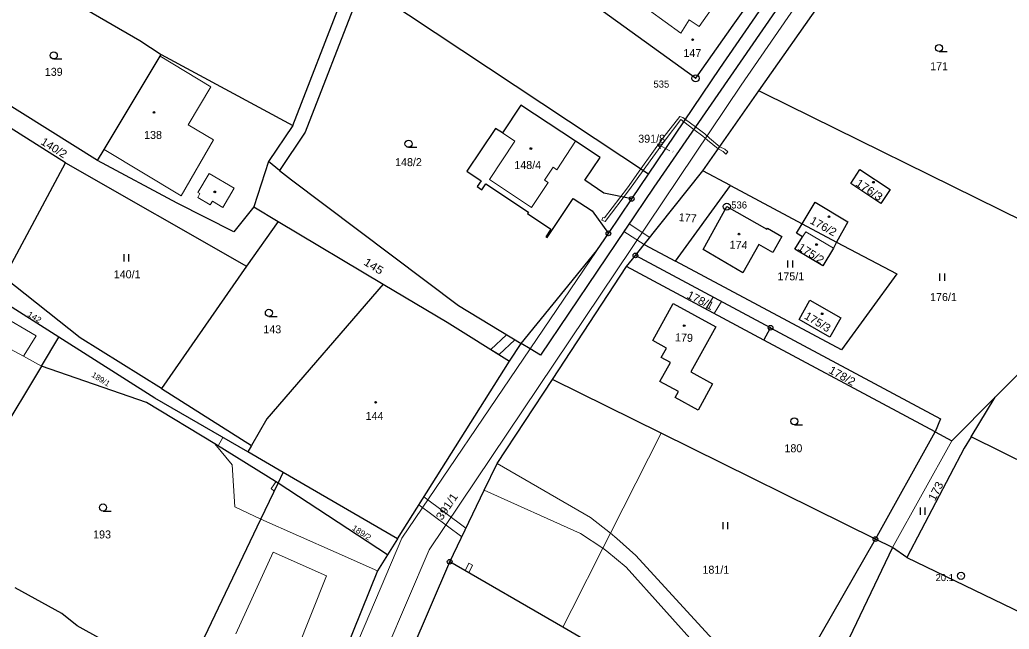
# Model space of a CAD drawing. Extents: x -504006 to -501322, y -1128098 to -1124665.
# Drawn here: x -502549.5 to -502339.3, y -1126661.3 to -1126531.9 of the extents above; entities that cross this region are included whole.
import ezdxf
from ezdxf.enums import TextEntityAlignment as Align

# ---------------------------------------------------------------- set-up
doc = ezdxf.new("R2010")
doc.units = 0
doc.header["$LTSCALE"] = 0.68
for name, color, linetype, lineweight in [('1', 7, 'Continuous', 25), ('13', 7, 'Continuous', 13), ('3', 7, 'Continuous', 25), ('4', 7, 'Continuous', 13), ('5', 7, 'Continuous', 25), ('7', 7, 'Continuous', 13), ('8', 7, 'Continuous', 25)]:
    doc.layers.add(name, color=color, linetype=linetype, lineweight=lineweight)
doc.layers.add('2', color=7, linetype='Continuous')

msp = doc.modelspace()

# ---------------------------------------------------------------- linework, layer by layer
at = {"layer": '1'}
for p, q in [((-502491.56, -1126554.34), (-502465.06, -1126486.12)), ((-502392.52, -1126547.01), (-502363.8, -1126506.1)), ((-502400.8, -1126542.27), (-502379.33, -1126511.02)), ((-502384.2, -1126523.11), (-502414.86, -1126567.45)), ((-502544.69, -1126524.32), (-502524.07, -1126536.28)), ((-502476.73, -1126524.43), (-502488.89, -1126555.75)), ((-502415.96, -1126564.65), (-502476.73, -1126524.43)), ((-502405.98, -1126544.33), (-502427.32, -1126528.97)), ((-502398.02, -1126533.04), (-502405.98, -1126544.33)), ((-502524.07, -1126536.28), (-502519.51, -1126539.28)), ((-502531.61, -1126559.43), (-502519.72, -1126539.62)), ((-502519.72, -1126539.62), (-502519.51, -1126539.28)), ((-502519.51, -1126539.28), (-502491.56, -1126554.34)), ((-502533.04, -1126561.8), (-502565.3, -1126541.54)), ((-502415.96, -1126564.65), (-502400.8, -1126542.27)), ((-502539.8, -1126562.27), (-502568.05, -1126544.45)), ((-502404.41, -1126563.95), (-502392.52, -1126547.01)), ((-502391.37, -1126547.57), (-502392.52, -1126547.01)), ((-502336.24, -1126574.75), (-502391.37, -1126547.57)), ((-502443.1, -1126550.02), (-502447, -1126555.93)), ((-502431.49, -1126557.7), (-502443.1, -1126550.02)), ((-502491.56, -1126554.34), (-502496.68, -1126562.02)), ((-502448.5, -1126554.96), (-502454.57, -1126564.07)), ((-502447, -1126555.93), (-502448.5, -1126554.96)), ((-502488.89, -1126555.75), (-502494.33, -1126563.91)), ((-502533.04, -1126561.8), (-502531.61, -1126559.43)), ((-502426.26, -1126561.18), (-502431.49, -1126557.7)), ((-502516.1, -1126570.87), (-502533.04, -1126561.8)), ((-502429.47, -1126565.99), (-502426.26, -1126561.18)), ((-502552.84, -1126586.64), (-502539.8, -1126562.27)), ((-502539.8, -1126562.27), (-502501.36, -1126584.22)), ((-502496.68, -1126562.02), (-502499.83, -1126571.64)), ((-502494.33, -1126563.91), (-502496.68, -1126562.02)), ((-502494.33, -1126563.91), (-502491.84, -1126565.92)), ((-502416.88, -1126579.61), (-502404.41, -1126563.95)), ((-502398.54, -1126567.07), (-502404.41, -1126563.95)), ((-502372.97, -1126566.7), (-502371.1, -1126563.66)), ((-502371.1, -1126563.66), (-502364.64, -1126567.93)), ((-502491.84, -1126565.92), (-502456.31, -1126592.6)), ((-502454.57, -1126564.07), (-502451.51, -1126566.08)), ((-502451.51, -1126566.08), (-502452.39, -1126567.33)), ((-502425.44, -1126568.69), (-502429.47, -1126565.99)), ((-502419.54, -1126569.95), (-502415.96, -1126564.65)), ((-502452.39, -1126567.33), (-502451.39, -1126568.01)), ((-502451.39, -1126568.01), (-502450.53, -1126566.75)), ((-502450.53, -1126566.75), (-502441.45, -1126572.74)), ((-502414.86, -1126567.45), (-502438.93, -1126603.12)), ((-502410.26, -1126583.15), (-502398.54, -1126567.07)), ((-502398.54, -1126567.07), (-502383.35, -1126575.2)), ((-502366.61, -1126570.91), (-502372.97, -1126566.7)), ((-502364.64, -1126567.93), (-502366.61, -1126570.91)), ((-502437.48, -1126578.1), (-502432, -1126569.82)), ((-502432, -1126569.82), (-502427.93, -1126572.47)), ((-502419.54, -1126569.95), (-502425.44, -1126568.69)), ((-502424.49, -1126577.25), (-502419.54, -1126569.95)), ((-502504.09, -1126576.9), (-502516.1, -1126570.87)), ((-502499.83, -1126571.64), (-502504.09, -1126576.9)), ((-502499.83, -1126571.64), (-502494.68, -1126574.71)), ((-502404.37, -1126580.7), (-502399.33, -1126571.57)), ((-502399.33, -1126571.57), (-502390.84, -1126576.39)), ((-502383.35, -1126575.2), (-502380.59, -1126570.6)), ((-502380.59, -1126570.6), (-502373.61, -1126574.8)), ((-502441.45, -1126572.74), (-502441.69, -1126573.07)), ((-502441.69, -1126573.07), (-502436.71, -1126576.35)), ((-502427.93, -1126572.47), (-502424.49, -1126577.25)), ((-502494.68, -1126574.71), (-502501.36, -1126584.22)), ((-502494.68, -1126574.71), (-502472.34, -1126588.01)), ((-502436.71, -1126576.35), (-502437.76, -1126577.98)), ((-502390.84, -1126576.39), (-502390.71, -1126576.17)), ((-502390.71, -1126576.17), (-502387.64, -1126577.91)), ((-502384.56, -1126577.21), (-502383.35, -1126575.2)), ((-502383.35, -1126575.2), (-502376, -1126579.13)), ((-502373.61, -1126574.8), (-502376, -1126579.13)), ((-502437.76, -1126577.98), (-502437.48, -1126578.1)), ((-502426.96, -1126580.9), (-502424.49, -1126577.25)), ((-502387.64, -1126577.91), (-502389.57, -1126581.3)), ((-502384.91, -1126580.64), (-502383.25, -1126577.98)), ((-502383.25, -1126577.98), (-502384.56, -1126577.21)), ((-502418.75, -1126581.95), (-502416.88, -1126579.61)), ((-502416.88, -1126579.61), (-502410.26, -1126583.15)), ((-502395.93, -1126585.65), (-502404.37, -1126580.7)), ((-502392.53, -1126579.63), (-502395.93, -1126585.65)), ((-502389.57, -1126581.3), (-502392.53, -1126579.63)), ((-502378.94, -1126584.18), (-502384.91, -1126580.64)), ((-502376.69, -1126580.38), (-502378.94, -1126584.18)), ((-502376, -1126579.13), (-502376.69, -1126580.38)), ((-502376, -1126579.13), (-502363.21, -1126585.83)), ((-502443.03, -1126600.64), (-502426.96, -1126580.9)), ((-502420.61, -1126584.3), (-502418.75, -1126581.95)), ((-502390.04, -1126597.31), (-502418.75, -1126581.95)), ((-502501.36, -1126584.22), (-502519.41, -1126610.18)), ((-502436.36, -1126608.25), (-502420.61, -1126584.3)), ((-502391.46, -1126599.92), (-502420.61, -1126584.3)), ((-502374.97, -1126602.01), (-502410.26, -1126583.15)), ((-502536.69, -1126599.46), (-502552.84, -1126586.64)), ((-502363.21, -1126585.83), (-502374.97, -1126602.01)), ((-502472.34, -1126588.01), (-502497.08, -1126616.67)), ((-502472.34, -1126588.01), (-502458.73, -1126596.12)), ((-502342.31, -1126612.01), (-502317.72, -1126587.26)), ((-502541.25, -1126599.31), (-502554.98, -1126590.62)), ((-502456.31, -1126592.6), (-502443.03, -1126600.64)), ((-502415.05, -1126600.03), (-502410.72, -1126592.13)), ((-502410.72, -1126592.13), (-502401.7, -1126597.07)), ((-502383.98, -1126595.53), (-502381.69, -1126591.45)), ((-502381.69, -1126591.45), (-502375.13, -1126595.21)), ((-502375.13, -1126595.21), (-502377.48, -1126599.3)), ((-502458.73, -1126596.12), (-502445.53, -1126604.37)), ((-502401.7, -1126597.07), (-502406.97, -1126606.69)), ((-502391.46, -1126599.92), (-502390.04, -1126597.31)), ((-502390.04, -1126597.31), (-502353.91, -1126616.65)), ((-502377.48, -1126599.3), (-502383.98, -1126595.53)), ((-502544.95, -1126605.46), (-502541.25, -1126599.31)), ((-502520.84, -1126612.23), (-502541.25, -1126599.31)), ((-502519.41, -1126610.18), (-502536.69, -1126599.46)), ((-502445.53, -1126604.37), (-502443.03, -1126600.64)), ((-502441.12, -1126601.8), (-502443.03, -1126600.64)), ((-502438.93, -1126603.12), (-502441.12, -1126601.8)), ((-502412.17, -1126601.61), (-502415.05, -1126600.03)), ((-502413.26, -1126603.6), (-502412.17, -1126601.61)), ((-502411.33, -1126604.66), (-502413.26, -1126603.6)), ((-502544.95, -1126605.46), (-502554.24, -1126620.87)), ((-502522.59, -1126613.18), (-502544.95, -1126605.46)), ((-502469.29, -1126642.13), (-502445.53, -1126604.37)), ((-502413.55, -1126608.7), (-502411.33, -1126604.66)), ((-502406.97, -1126606.69), (-502402.36, -1126609.22)), ((-502519.41, -1126610.18), (-502500.34, -1126622.32)), ((-502448.12, -1126626.12), (-502436.36, -1126608.25)), ((-502413.29, -1126619.66), (-502436.36, -1126608.25)), ((-502409.63, -1126610.84), (-502413.55, -1126608.7)), ((-502402.36, -1126609.22), (-502405.4, -1126614.77)), ((-502501.12, -1126623.67), (-502520.84, -1126612.23)), ((-502410.31, -1126612.08), (-502409.63, -1126610.84)), ((-502405.4, -1126614.77), (-502410.31, -1126612.08)), ((-502351.55, -1126621.3), (-502342.31, -1126612.01)), ((-502347.44, -1126620.43), (-502342.31, -1126612.01)), ((-502508.13, -1126621.92), (-502522.59, -1126613.18)), ((-502497.08, -1126616.67), (-502500.34, -1126622.32)), ((-502367.75, -1126642.18), (-502413.29, -1126619.66)), ((-502367.75, -1126642.18), (-502355.08, -1126619.41)), ((-502355.08, -1126619.41), (-502351.55, -1126621.3)), ((-502347.44, -1126620.43), (-502348.93, -1126622.89)), ((-502331.98, -1126628.1), (-502347.44, -1126620.43)), ((-502494.68, -1126630.29), (-502508.13, -1126621.92)), ((-502500.34, -1126622.32), (-502501.12, -1126623.67)), ((-502493.6, -1126628.03), (-502501.12, -1126623.67)), ((-502348.93, -1126622.89), (-502361.11, -1126646.11)), ((-502450.87, -1126631.81), (-502448.12, -1126626.12)), ((-502494.68, -1126630.29), (-502493.6, -1126628.03)), ((-502469.29, -1126642.13), (-502493.6, -1126628.03)), ((-502498.34, -1126637.96), (-502494.68, -1126630.29)), ((-502471.42, -1126645.51), (-502494.68, -1126630.29)), ((-502458.21, -1126646.98), (-502450.87, -1126631.81)), ((-502514.61, -1126672.05), (-502498.34, -1126637.96)), ((-502469.29, -1126642.13), (-502471.42, -1126645.51)), ((-502388.53, -1126678.42), (-502367.75, -1126642.18)), ((-502364.16, -1126643.95), (-502367.75, -1126642.18)), ((-502471.42, -1126645.51), (-502473.55, -1126648.9)), ((-502361.11, -1126646.11), (-502364.16, -1126643.95)), ((-502468.87, -1126671.79), (-502458.21, -1126646.98)), ((-502434.16, -1126660.88), (-502458.21, -1126646.98)), ((-502361.11, -1126646.11), (-502297.3, -1126676.83)), ((-502473.55, -1126648.9), (-502487.98, -1126684.63)), ((-502540.59, -1126658), (-502550.55, -1126652.54)), ((-502537.38, -1126660.61), (-502540.59, -1126658)), ((-502532.13, -1126663.52), (-502537.38, -1126660.61)), ((-502394.44, -1126683.84), (-502434.16, -1126660.88))]:
    msp.add_line(p, q, dxfattribs=at)
for points in [[(-502382.43, -1126510.29), (-502390.84, -1126522.88), (-502398.02, -1126533.04)], [(-502353.91, -1126616.65), (-502355.08, -1126619.41), (-502391.46, -1126599.92)], [(-502364.16, -1126643.95), (-502383.3, -1126684.1), (-502385.94, -1126688.76)]]:
    msp.add_lwpolyline(points, dxfattribs=at)
at = {"layer": '13'}
for points in [[(-502408.44, -1126553.55), (-502408.13, -1126553.09), (-502408.68, -1126552.65), (-502409.34, -1126552.46), (-502412.96, -1126557.07), (-502417.61, -1126563.56), (-502417.1, -1126563.9), (-502412.45, -1126557.45), (-502409.08, -1126553.1)], [(-502408.13, -1126553.09), (-502408.44, -1126553.55), (-502406.37, -1126555.17), (-502404.42, -1126556.6), (-502403.41, -1126557.47), (-502401.15, -1126559.31), (-502400.83, -1126558.85), (-502403.04, -1126557.03), (-502404.03, -1126556.11), (-502406.01, -1126554.65)], [(-502400.83, -1126558.85), (-502401.15, -1126559.31), (-502400.14, -1126559.85), (-502399.51, -1126560.43), (-502399.15, -1126559.97), (-502399.76, -1126559.38)], [(-502425.64, -1126573.87), (-502425.86, -1126574.44), (-502425.15, -1126574.71), (-502420.02, -1126567.93), (-502417.1, -1126563.9), (-502417.61, -1126563.56), (-502420.46, -1126567.57), (-502425.35, -1126573.98)], [(-502415.7, -1126578.13), (-502420.11, -1126575.23), (-502421.2, -1126576.84), (-502416.88, -1126579.61)], [(-502402.25, -1126590.78), (-502403.8, -1126593.31), (-502402.03, -1126594.26), (-502400.48, -1126591.72)], [(-502446.13, -1126598.77), (-502449.47, -1126601.91), (-502447.72, -1126603), (-502444.35, -1126599.84)], [(-502507.42, -1126622.36), (-502494.68, -1126630.29), (-502493.6, -1126628.03), (-502501.12, -1126623.67), (-502506.4, -1126620.61)], [(-502496.15, -1126631.45), (-502495.5, -1126632), (-502494.68, -1126630.29), (-502495.15, -1126630), (-502495.68, -1126630.86)], [(-502454.75, -1126639.83), (-502463.68, -1126633.22), (-502464.75, -1126634.91), (-502455.64, -1126641.66)], [(-502454.9, -1126648.89), (-502454.11, -1126649.35), (-502453.35, -1126647.72), (-502454.14, -1126647.29)]]:
    msp.add_lwpolyline(points, close=True, dxfattribs=at)
at = {"layer": '3'}
for p, q in [((-502354.243, -1126538.65), (-502352.493, -1126538.65)), ((-502542.323, -1126540.22), (-502540.573, -1126540.22)), ((-502466.953, -1126558.98), (-502465.203, -1126558.98)), ((-502527.381, -1126583.2), (-502527.381, -1126581.7)), ((-502526.38, -1126583.2), (-502526.38, -1126581.7)), ((-502386.341, -1126584.5), (-502386.341, -1126583)), ((-502385.34, -1126584.5), (-502385.34, -1126583)), ((-502354.051, -1126587.3), (-502354.051, -1126585.8)), ((-502353.05, -1126587.3), (-502353.05, -1126585.8)), ((-502496.613, -1126594.88), (-502494.863, -1126594.88)), ((-502384.983, -1126617.91), (-502383.233, -1126617.91)), ((-502531.853, -1126636.21), (-502530.103, -1126636.21)), ((-502358.211, -1126636.99), (-502358.211, -1126635.49)), ((-502357.21, -1126636.99), (-502357.21, -1126635.49)), ((-502400.091, -1126640.07), (-502400.091, -1126638.57)), ((-502399.09, -1126640.07), (-502399.09, -1126638.57))]:
    msp.add_line(p, q, dxfattribs=at)
for centre in [(-502542.3229, -1126539.4698), (-502354.2429, -1126537.8998), (-502466.9529, -1126558.2298), (-502496.6129, -1126594.1298), (-502384.9829, -1126617.1598), (-502531.8529, -1126635.4598)]:
    msp.add_circle(centre, 0.75, dxfattribs=at)
at = {"layer": '4'}
for p, q in [((-502370.24, -1126508), (-502396.3, -1126545.8)), ((-502405.22, -1126533.31), (-502399.58, -1126525.35)), ((-502419.12, -1126527.46), (-502409.09, -1126534.74)), ((-502409.09, -1126534.74), (-502407.3, -1126531.91)), ((-502407.3, -1126531.91), (-502405.22, -1126533.31)), ((-502519.72, -1126539.62), (-502508.94, -1126546.13)), ((-502508.94, -1126546.13), (-502513.8, -1126554.23)), ((-502396.3, -1126545.8), (-502462.54, -1126644.48)), ((-502513.8, -1126554.23), (-502508.36, -1126557.38)), ((-502508.36, -1126557.38), (-502515.23, -1126569.25)), ((-502449.77, -1126565.8), (-502444.38, -1126557.67)), ((-502444.38, -1126557.67), (-502447, -1126555.93)), ((-502515.23, -1126569.25), (-502531.61, -1126559.43)), ((-502431.49, -1126557.7), (-502435.48, -1126563.73)), ((-502436.24, -1126563.23), (-502438.04, -1126565.94)), ((-502435.48, -1126563.73), (-502436.24, -1126563.23)), ((-502511.68, -1126568.58), (-502509.28, -1126564.53)), ((-502509.28, -1126564.53), (-502504.02, -1126567.64)), ((-502440.81, -1126571.75), (-502449.77, -1126565.8)), ((-502438.04, -1126565.94), (-502437.29, -1126566.43)), ((-502504.02, -1126567.64), (-502506.39, -1126571.78)), ((-502437.29, -1126566.43), (-502440.81, -1126571.75)), ((-502511.74, -1126569.62), (-502511.27, -1126568.82)), ((-502509.07, -1126571.23), (-502511.74, -1126569.62)), ((-502511.27, -1126568.82), (-502511.68, -1126568.58)), ((-502508.59, -1126570.45), (-502509.07, -1126571.23)), ((-502506.39, -1126571.78), (-502508.59, -1126570.45)), ((-502383.25, -1126577.98), (-502382.58, -1126576.9)), ((-502382.58, -1126576.9), (-502376.69, -1126580.38)), ((-502441.12, -1126601.8), (-502426.96, -1126580.9)), ((-502553.84, -1126594.48), (-502546.08, -1126598.99)), ((-502548.78, -1126603.34), (-502556.72, -1126599.01)), ((-502546.08, -1126598.99), (-502548.64, -1126603.12)), ((-502468.35, -1126642), (-502441.12, -1126601.8)), ((-502548.64, -1126603.12), (-502548.78, -1126603.34)), ((-502548.78, -1126603.34), (-502544.95, -1126605.46)), ((-502424.04, -1126640.9), (-502413.29, -1126619.66)), ((-502508.13, -1126621.92), (-502504.39, -1126626.43)), ((-502351.55, -1126621.3), (-502364.16, -1126643.95)), ((-502504.39, -1126626.43), (-502503.86, -1126635.33)), ((-502448.12, -1126626.12), (-502428.27, -1126637.61)), ((-502450.87, -1126631.81), (-502430.42, -1126640.99)), ((-502503.86, -1126635.33), (-502498.34, -1126637.96)), ((-502498.34, -1126637.96), (-502482.36, -1126645.01)), ((-502424.04, -1126640.9), (-502428.27, -1126637.61)), ((-502430.42, -1126640.99), (-502425.66, -1126644.09)), ((-502425.66, -1126644.09), (-502424.04, -1126640.9)), ((-502422.69, -1126642.08), (-502424.04, -1126640.9)), ((-502468.35, -1126642), (-502488.41, -1126689.01)), ((-502418.68, -1126645.66), (-502422.69, -1126642.08)), ((-502503.66, -1126662.3), (-502495.74, -1126644.98)), ((-502495.74, -1126644.98), (-502484.35, -1126649.98)), ((-502462.54, -1126644.48), (-502482.56, -1126690.99)), ((-502482.36, -1126645.01), (-502473.55, -1126648.9)), ((-502432.26, -1126657.13), (-502425.66, -1126644.09)), ((-502425.66, -1126644.09), (-502424.82, -1126644.72)), ((-502424.82, -1126644.72), (-502420.74, -1126648.16)), ((-502418.68, -1126645.66), (-502388.53, -1126678.42)), ((-502484.35, -1126649.98), (-502492.98, -1126671.58)), ((-502420.74, -1126648.16), (-502390.44, -1126681.76)), ((-502434.16, -1126660.88), (-502432.26, -1126657.13))]:
    msp.add_line(p, q, dxfattribs=at)
at = {"layer": '5'}
for centre in [(-502406.5968, -1126536.1292), (-502521.0268, -1126551.5792), (-502440.9668, -1126559.2492), (-502368.1768, -1126566.3892), (-502508.1168, -1126568.4392), (-502377.6368, -1126573.7392), (-502396.7368, -1126577.4192), (-502380.2768, -1126579.6292), (-502379.0768, -1126594.3292), (-502408.3868, -1126596.8492), (-502473.9468, -1126613.1192)]:
    msp.add_circle(centre, 0.175, dxfattribs=at)
at = {"layer": '7'}
msp.add_line((-502414.065, -1126558.295), (-502413.432, -1126559.219), dxfattribs=at)
msp.add_lwpolyline([(-502411.44, -1126559.75), (-502414.065, -1126558.295), (-502412.946, -1126558.343)], dxfattribs=at)
at = {"layer": '8'}
for centre, radius in [((-502405.98, -1126544.3298), 0.75), ((-502405.98, -1126544.3298), 0.03), ((-502419.54, -1126569.9499), 0.5), ((-502419.54, -1126569.9499), 0.0303), ((-502399.33, -1126571.5698), 0.75), ((-502399.33, -1126571.5698), 0.03), ((-502424.49, -1126577.2499), 0.5), ((-502424.49, -1126577.2499), 0.0303), ((-502418.75, -1126581.9499), 0.5), ((-502418.75, -1126581.9499), 0.0303), ((-502390.04, -1126597.3099), 0.5), ((-502390.04, -1126597.3099), 0.0303), ((-502367.75, -1126642.1799), 0.5), ((-502367.75, -1126642.1799), 0.0303), ((-502458.21, -1126646.9799), 0.5), ((-502458.21, -1126646.9799), 0.0303), ((-502349.58, -1126649.9798), 0.75), ((-502349.58, -1126649.9798), 0.03)]:
    msp.add_circle(centre, radius, dxfattribs=at)

# ---------------------------------------------------------------- texts
at = {"layer": '2'}
for s, p in [('147', (-502406.649, -1126539.805)), ('139', (-502542.329, -1126543.805)), ('171', (-502354.239, -1126542.625)), ('138', (-502521.229, -1126557.205)), ('148/2', (-502466.96, -1126562.985)), ('148/4', (-502441.63, -1126563.595)), ('140/1', (-502526.73, -1126586.795)), ('175/1', (-502385.74, -1126587.225)), ('176/1', (-502353.31, -1126591.625)), ('143', (-502495.899, -1126598.475)), ('144', (-502474.179, -1126616.875)), ('180', (-502385.189, -1126623.735)), ('193', (-502532.059, -1126642.035)), ('181/1', (-502401.66, -1126649.525))]:
    msp.add_text(s, height=1.7, dxfattribs=at).set_placement(p, align=Align.CENTER)
for s, height, rotation, width, p in [('140/2', 1.7, 328, 1.05, (-502542.7159, -1126559.8029)), ('391/8', 0.2, 56, 1.1, (-502410.7492, -1126560.0889)), ('176/3', 1.7, 326, 1.1, (-502369.5548, -1126568.7251)), ('176/2', 1.7, 331, 1.05, (-502379.2256, -1126576.4873)), ('175/2', 1.7, 328, 1.05, (-502381.8759, -1126582.2429)), ('145', 1.7, 328, 1.15, (-502474.7949, -1126584.9434)), ('142', 1.2, 328, 1.15, (-502546.716, -1126595.5256)), ('175/3', 1.7, 329, 1.05, (-502380.4753, -1126596.7875)), ('189/1', 1.2, 328, 1.05, (-502532.6265, -1126608.725)), ('173', 1.7, 63, 1.1, (-502354.1903, -1126632.3854)), ('391/1', 1.7, 56, 1.1, (-502458.1139, -1126635.7348)), ('189/2', 1.2, 327, 1.1, (-502477.2368, -1126641.3093))]:
    msp.add_text(s, height=height, rotation=rotation, dxfattribs=dict(at, width=width)).set_placement(p, align=Align.CENTER)
msp.add_text('391/8', height=1.7, dxfattribs=at).set_placement((-502412.46, -1126558.005), align=Align.RIGHT)
for s, rotation, p in [('177', 355, (-502407.7186, -1126574.7961)), ('174', 358, (-502396.8592, -1126580.5545)), ('179', 358, (-502408.4592, -1126600.2445))]:
    msp.add_text(s, height=1.7, rotation=rotation, dxfattribs=at).set_placement(p, align=Align.CENTER)
at = {"layer": '2', "width": 1.05}
for s, rotation, p in [('178/1', 333, (-502407.992, -1126590.868)), ('178/2', 331, (-502377.836, -1126606.801))]:
    msp.add_text(s, height=1.7, rotation=rotation, dxfattribs=at).set_placement(p)
at = {"layer": '8'}
for s, p in [('535', (-502411.569, -1126546.305)), ('536', (-502395.039, -1126571.975)), ('20.1', (-502351.079, -1126651.097))]:
    msp.add_text(s, height=1.5, dxfattribs=at).set_placement(p, align=Align.RIGHT)

doc.saveas('drawing.dxf')
